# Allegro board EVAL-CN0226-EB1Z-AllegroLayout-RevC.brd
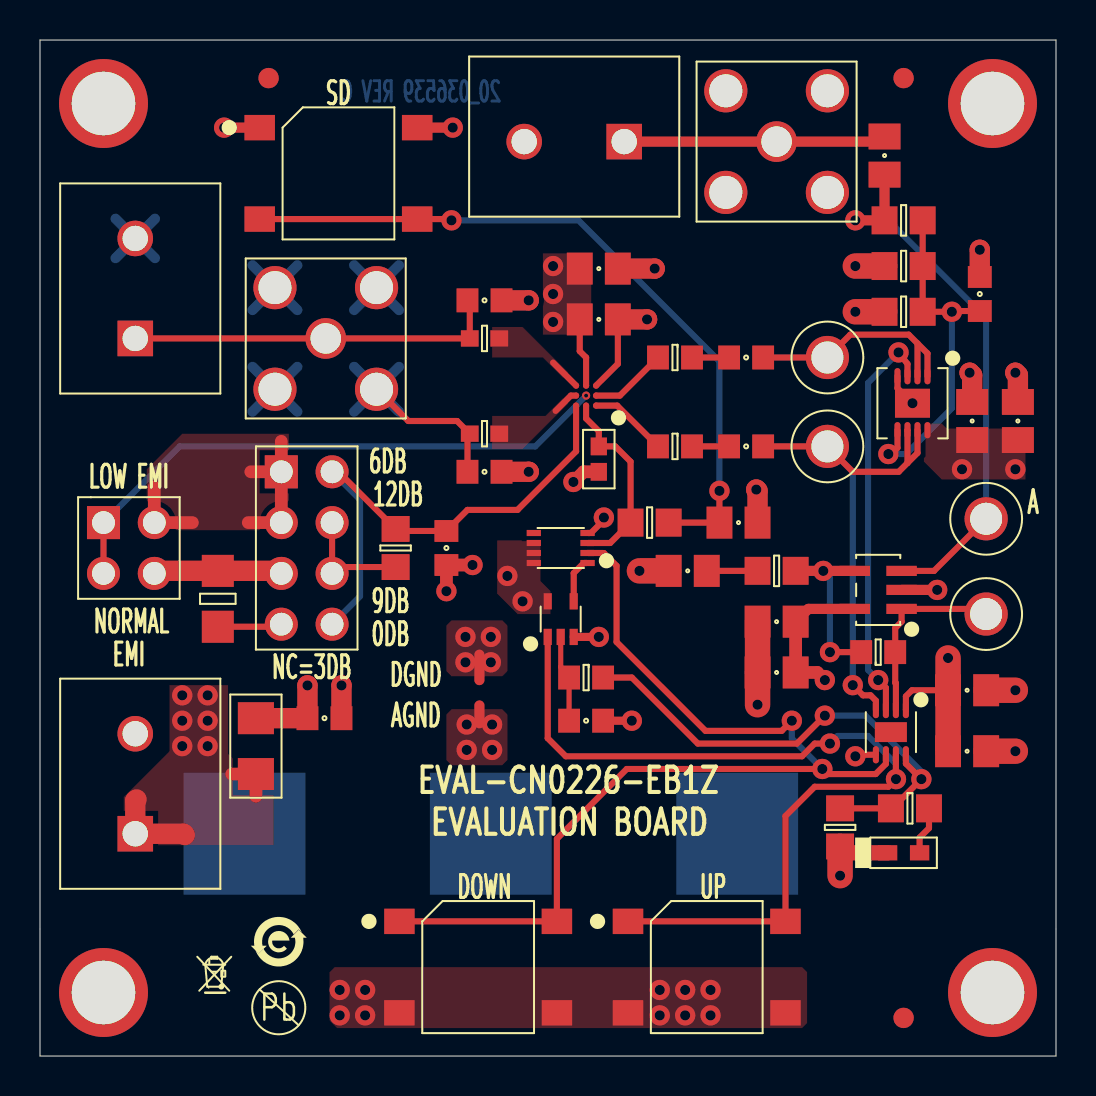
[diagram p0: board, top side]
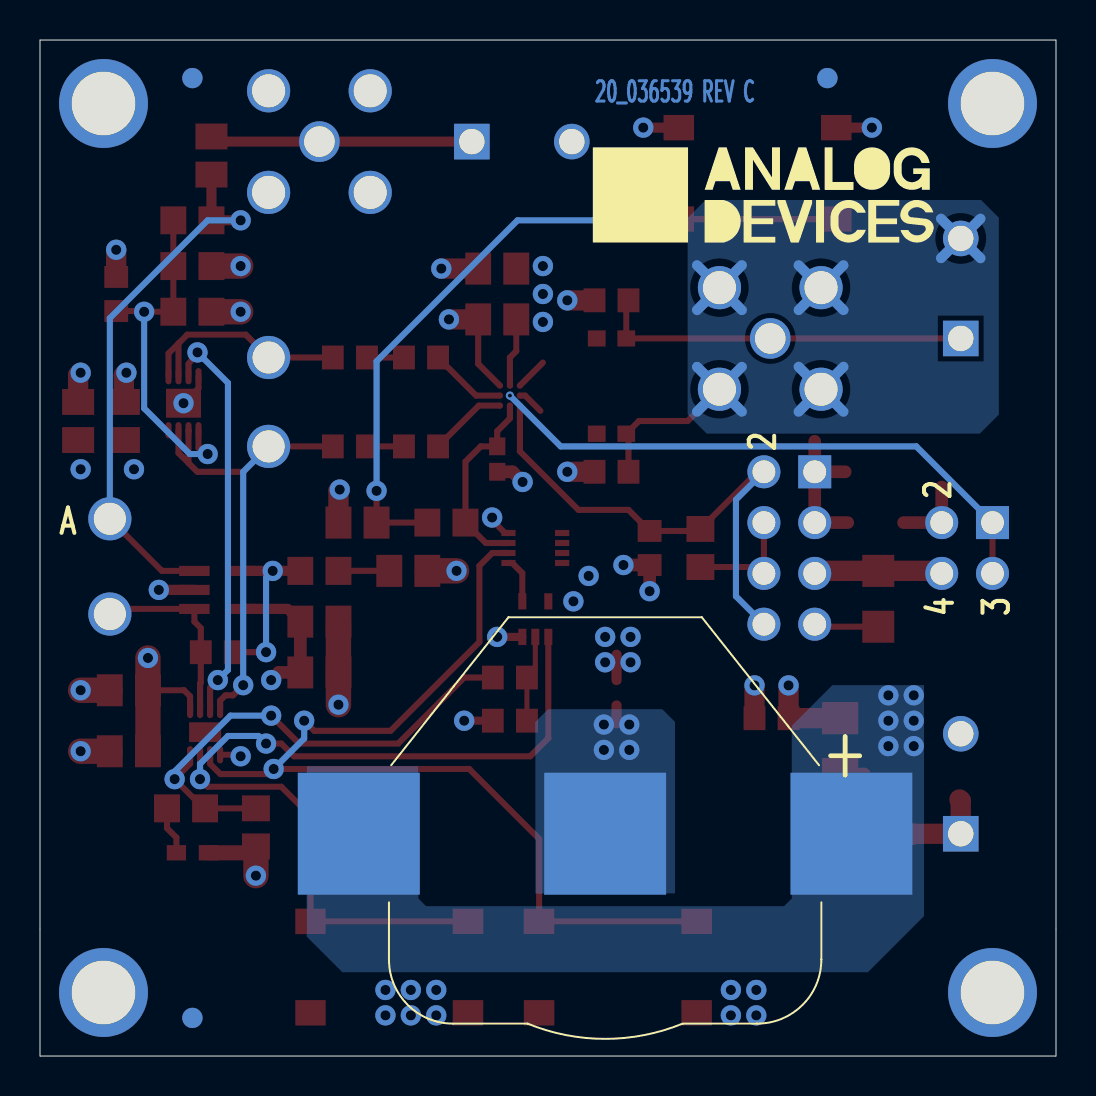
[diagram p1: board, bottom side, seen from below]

Outline 50.8 x 50.8 mm; copper layers: TOP, L2_GND, L3_POWER, BOTTOM. Coordinates in mm from the lower left corner of the outline.
Outline path: 0,50.8 0,0 50.8,0 50.8,50.8 0,50.8

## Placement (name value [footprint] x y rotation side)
A1  ADA4051-2ACPZ  [QFN8_3X3_PAD1_75X1_45]  43.62 32.64 180 top
A3  AD8515ARTZ  [SOT23-5L]  41.91 23.3 90 top
BT1  N/A  [BTCR2032_SKTBK883]  22.54 11.11 0 bottom
C1  0.1uF  [C0805]  27.94 36.83 180 top
C2  0.047uF  [C0603]  35.31 34.92 180 top
C3  0.047uF  [C0603]  35.31 30.48 180 top
C4  0.1uF  [C0805]  36.83 21.72 0 top
C5  10uF  [C0805H60]  36.83 19.18 0 top
C6  10uF  [C0805H60]  46.35 18.29 180 top
C7  0.1uF  [C0805]  46.35 15.24 180 top
C8  1uF  [C0603]  46.99 38.1 270 top
C9  0.22UF  [C0805]  42.23 45.02 270 top
C10  0.1uF  [C0805]  34.92 26.67 180 top
C11  10uF  [C0805H60]  27.94 39.37 180 top
C12  1.5uF  [C0805]  32.38 24.26 0 top
C13  1uF  [C0603]  14.22 16.89 180 top
C14  10uF  [C0805H60]  48.89 31.75 270 top
C15  0.1uF  [C0805]  46.61 31.75 270 top
C16  510pF  [C0603]  22.23 29.21 180 top
C17  510pF  [C0603]  22.23 37.78 0 top
C18  2.2uF  [C0603]  20.32 25.4 90 top
C19  0.1UF  [C0603]  27.3 16.76 0 top
DS1  LTST-C190CKT  [LED0603]  43.18 10.16 0 top
E1  220OHM  [L0603]  22.23 31.11 180 top
E2  220OHM  [L0603]  22.23 35.88 180 top
E3  600OHM AT 100MEGHZ  [L1206-3]  10.79 15.49 90 top
IN+  RED  [CNLOOPTP]  39.37 34.92 0 top
IN-  RED  [CNLOOPTP]  39.37 30.48 0 top
INPUT  RED  [CNLOOPTP]  47.31 22.1 0 top
J1  5-1814832-1  [CNTYCO1814832]  14.29 35.88 0 top
J2  5-1814832-1  [CNTYCO1814832]  36.83 45.72 0 top
J3  CTB5000/2  [CN1X2H394]  4.76 11.11 90 top
NOREF  -  []  3.17 47.62 0 top
NOREF#2  -  []  11.94 5.72 0 top
NOREF#3  -  [unnamed#2]  47.62 3.17 90 top
NOREF#4  -  []  0 50.8 0 top
NOREF#5  -  [unnamed#2]  43.18 48.9 0 top
NOREF#6  -  []  50.8 50.8 180 top
NOREF#7  -  [unnamed#2]  3.17 47.62 90 top
NOREF#8  -  []  50.8 0 90 top
NOREF#9  -  []  0 50.8 0 top
NOREF#10  -  []  50.8 0 90 top
NOREF#11  -  []  0 0 0 top
NOREF#12  -  [unnamed#2]  11.43 48.9 0 top
NOREF#13  -  []  0 50.8 270 top
NOREF#14  -  []  376.69 133.29 0 top
NOREF#15  -  []  0 0 0 top
NOREF#16  -  []  0 0 0 top
NOREF#17  -  []  8.76 4.06 0 top
NOREF#18  -  [unnamed#2]  43.18 1.91 0 top
NOREF#19  -  []  -182.88 -227.33 0 top
NOREF#20  -  []  178.44 265.18 0 top
NOREF#21  -  []  -49.78 224.92 0 top
NOREF#22  -  []  -175.26 -218.19 0 top
NOREF#23  -  [unnamed#2]  47.62 47.62 90 top
NOREF#24  -  []  3.17 47.62 0 top
NOREF#25  -  []  46.61 65.41 0 top
NOREF#26  -  [unnamed#2]  3.17 3.17 90 top
NOREF#27  -  []  -184.15 -228.6 0 top
NOREF#28  -  []  50.8 50.8 0 top
NOREF#29  -  []  11.94 2.41 0 top
NOREF#30  -  [unnamed#2]  43.18 1.91 180 bottom
NOREF#31  -  []  14.61 43.05 180 bottom
NOREF#32  -  [unnamed#2]  11.43 48.9 180 bottom
NOREF#33  -  [unnamed#2]  43.18 48.9 180 bottom
P1  CTB5000/2  [CN1X2H394]  4.76 35.88 90 top
P2  CTB5000/2  [CN1X2H394]  29.21 45.72 180 top
P3  TSW-102-08-G-D  [CNSAMTEC2X2H338LD36]  3.17 26.67 270 top
P4  TSW-104-08-T-D  [CNSAMTEC2X4H330LD36]  12.07 29.21 270 top
R1  0  [R0603]  31.75 34.92 180 top
R2  33K  [R0805]  43.18 37.21 180 top
R3  33K  [R0805]  43.18 39.5 0 top
R4  0  [R0603]  41.91 20.19 0 top
R5  47K  [R0805]  17.78 25.4 270 top
R6  44.2K  [R0402]  27.94 29.84 270 top
R7  1.8K  [R0805]  43.5 12.38 0 top
R8  110K  [R0805]  40 11.43 270 top
R9  33K  [R0805]  43.18 41.78 0 top
R10  0  [R0603]  31.75 30.48 180 top
R11  10K  [R0805]  36.83 24.26 0 top
R12  1.8K  [R0805]  30.48 26.67 0 top
R13  0  [R1206]  8.89 22.86 270 top
R14  430K  [R0603]  27.3 18.92 180 top
S1  B3S-1000  [SWB3S1000]  14.92 44.13 180 top
S2  B3S-1000  [SWB3S1000]  33.34 4.45 180 top
S3  B3S-1000  [SWB3S1000]  21.91 4.45 180 top
SNS1  SNS  [NCSNS20MIL]  21.97 18.8 270 top
TP4  RED  [CNLOOPTP]  47.31 26.86 0 top
U1  SSM2375_PRELIM  [WLCSP9]  27.3 33.02 90 top
U2  NC7SZ32P5X  [SC70-5]  26.04 21.84 0 top
U3  AD5116BCPZ5  [QFN8_2X2_PAD1_6X1]  42.54 16.19 180 top
U4  NC7SZ74K8X  [US8]  26.04 25.4 90 top

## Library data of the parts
A1 = ADA4051_2_V2: User Part Number: UPN; Tolerance: N/A; alternate symbols: (); part number: ADA4051_2_V2_SM-ADA4051-2ACPZ,E018809,QFN8_3X3_PAD1_75X1_45; tolerance: N/A
A3 = AD8515: User Part Number: UPN; Tolerance: N/A; alternate symbols: (); part number: AD8515_SM-AD8515ARTZ,E017419,SOT23-5L; tolerance: N/A
BT1 = BAT3P: User Part Number: UPN; alternate symbols: (BTCR2032_SKTBK883_ALT); part number: BAT3P_SM-N/A,3V,E017318,BTCR2032_SKTBK883
C1 C4 C7 C10 C15 = CAP: Tolerance: 5; User Part Number: UPN; alternate symbols: (); part number: CAP_SM-0.1UF,50V,5,E015576,C0805; tolerance: 5
C2 C3 = CAP: Tolerance: 5; User Part Number: UPN; alternate symbols: (); part number: CAP_SM-0.047UF,25V,5,E012692,C0603; tolerance: 5
C5 C6 C11 C14 = CAP: Tolerance: 10; User Part Number: UPN; alternate symbols: (); part number: CAP_SM-10UF,10V,10,E011045,C0805H60; tolerance: 10
C8 C13 = CAP: Tolerance: 10; User Part Number: UPN; alternate symbols: (); part number: CAP_SM-1UF,25V,10,E006992,C0603; tolerance: 10
C9 = CAP: Tolerance: 10; User Part Number: UPN; alternate symbols: (); part number: CAP_SM-0.22UF,16V,10,E000443,C0805; tolerance: 10
C12 = CAP: Tolerance: 10; User Part Number: UPN; alternate symbols: (); part number: CAP_SM-1.5UF,6.3V,10,E012852,C0805; tolerance: 10
C16 C17 = CAP: Tolerance: 5; User Part Number: UPN; alternate symbols: (); part number: CAP_SM-510PF,50V,5,E010642,C0603; tolerance: 5
C18 = CAP: Tolerance: 10; User Part Number: UPN; alternate symbols: (); part number: CAP_SM-2.2UF,6.3V,10,E006877,C0603; tolerance: 10
C19 = CAP: Tolerance: 10; User Part Number: UPN; alternate symbols: (); part number: CAP_SM-0.1UF,25V,10,E007204,C0603; tolerance: 10
DS1 = DIOLED: Tolerance: N/A; User Part Number: UPN; alternate symbols: (); part number: DIOLED_SM-LTST-C190CKT,N/A,N/A,E023763,LED0603; tolerance: N/A
E1 E2 = FERRITE: Tolerance: 25; User Part Number: UPN; alternate symbols: (); part number: FERRITE_SM-220OHM,25,E006275,L0603; tolerance: 25
E3 = FERRITE: Tolerance: 25; User Part Number: UPN; alternate symbols: (); part number: FERRITE_SM-600OHM AT 100MEGHZ,25,E026440,L1206-3; tolerance: 25
IN+ IN- INPUT TP4 = CNTP1P: Tolerance: N/A; User Part Number: UPN; alternate symbols: (); part number: CNTP1P_TH-RED,E000947,CNLOOPTP; tolerance: N/A
J1 J2 = CNBNC5P: Tolerance: N/A; User Part Number: UPN; alternate symbols: (); part number: CNBNC5P_TH-5-1814832-1,E010606,CNTYCO1814832; tolerance: N/A
J3 P1 P2 = CN2P: Tolerance: N/A; User Part Number: UPN; alternate symbols: (); part number: CN2P_TH-CTB5000/2,E017604,CN1X2H394; tolerance: N/A
P3 = CN4P_ODD_EVEN: User Part Number: UPN; Tolerance: N/A; alternate symbols: (); part number: CN4P_ODD_EVEN_TH-TSW-102-08-G-D,E006588,CNSAMTEC2X2H338LD36; tolerance: N/A
P4 = CN8P_ODD_EVEN: User Part Number: UPN; Tolerance: N/A; alternate symbols: (); part number: CN8P_ODD_EVEN_TH-TSW-104-08-T-D,E006295,CNSAMTEC2X4H330LD36; tolerance: N/A
R1 R4 R10 = RES: Tolerance: 1; User Part Number: UPN; alternate symbols: (); part number: RES_SM-0,E004207,1/16W,1,R0603; tolerance: 1
R2 R3 R9 = RES: Tolerance: 1; User Part Number: UPN; alternate symbols: (); part number: RES_SM-33K,E004180,1/10W,1,R0805; tolerance: 1
R5 = RES: Tolerance: 1; User Part Number: UPN; alternate symbols: (); part number: RES_SM-47K,E016886,1/8W,1,R0805; tolerance: 1
R6 = RES: Tolerance: 1; User Part Number: UPN; alternate symbols: (); part number: RES_SM-44.2K,E023712,1/10W,1,R0402; tolerance: 1
R7 R12 = RES: Tolerance: 0.1; User Part Number: UPN; alternate symbols: (); part number: RES_SM-1.8K,E003814,1/10W,0.1,R0805; tolerance: 0.1
R8 = RES: Tolerance: 0.1; User Part Number: UPN; alternate symbols: (); part number: RES_SM-110K,E010949,1/8W,0.1,R0805; tolerance: 0.1
R11 = RES: Tolerance: 1; User Part Number: UPN; alternate symbols: (); part number: RES_SM-10K,E003254,1/8W,1,R0805; tolerance: 1
R13 = RES: Tolerance: 5; User Part Number: UPN; alternate symbols: (); part number: RES_SM-0,E010093,1/4W,5,R1206; tolerance: 5
R14 = RES: Tolerance: 1; User Part Number: UPN; alternate symbols: (); part number: RES_SM-430K,E011184,1/10W,1,R0603; tolerance: 1
S1-S3 = SWSPST4PIN: User Part Number: UPN; Tolerance: N/A; alternate symbols: (); part number: SWSPST4PIN_SM-B3S-1000,E004572,SWB3S1000; tolerance: N/A
SNS1 = NCSENSE: User Part Number: UPN; Tolerance: N/A; alternate symbols: (); part number: NCSENSE_SM-SNS,E005724,NCSNS20MIL; tolerance: N/A
U1 = SSM2375_PRELIM: Tolerance: N/A; User Part Number: UPN; alternate symbols: (); part number: SSM2375_PRELIM_SM-SSM2375_PRELIM,E011439,WLCSP9; tolerance: N/A
U2 = ICNC7SZ32: Tolerance: N/A; User Part Number: UPN; alternate symbols: (); part number: ICNC7SZ32_SM-NC7SZ32P5X,E007299,SC70-5; tolerance: N/A
U3 = AD511X: User Part Number: UPN; Tolerance: N/A; alternate symbols: (); part number: AD511X_SM-AD5116BCPZ5,E017320,QFN8_2X2_PAD1_6X1; tolerance: N/A
U4 = CMOSNC7SZ74: Tolerance: N/A; User Part Number: UPN; alternate symbols: (); part number: CMOSNC7SZ74_SM-NC7SZ74K8X,E012799,US8; tolerance: N/A

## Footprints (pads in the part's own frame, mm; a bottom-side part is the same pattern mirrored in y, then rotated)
BTCR2032_SKTBK883
  rect 6.096x6.096 smd: 1(-12.317,0) 2(12.317,0) 3(0,0)
C0603
  rect 1.092x1.194 smd: 1(-0.851,0) 2(0.851,0)
C0805
  rect 1.295x1.6 smd: 1(-0.953,0) 2(0.953,0)
C0805H60
  rect 1.295x1.6 smd: 1(-0.953,0) 2(0.953,0)
CN1X2H394
  rect 1.778x1.778 hole 1.27: 1(0,0)
  round 1.778 hole 1.27: 2(5,0)
CNLOOPTP
  round 2.159 hole 1.6: 1(0,0)
CNSAMTEC2X2H338LD36
  rect 1.651x1.651 hole 1.143: 1(0,0)
  round 1.651 hole 1.143: 2(0,2.54) 3(2.54,0) 4(2.54,2.54)
CNSAMTEC2X4H330LD36
  rect 1.651x1.651 hole 1.143: 1(0,0)
  round 1.651 hole 1.143: 2(0,2.54) 3(2.54,0) 4(2.54,2.54) 5(5.08,0) 6(5.08,2.54) 7(7.62,0) 8(7.62,2.54)
CNTYCO1814832
  round 2.032 hole 1.524: 1(0,0)
  round 2.159 hole 1.651: 2(-2.54,2.54) 3(2.54,2.54) 4(2.54,-2.54) 5(-2.54,-2.54)
L0603
  rect 0.889x0.813 smd: 1(-0.737,0) 2(0.737,0)
L1206-3
  rect 1.6x1.803 smd: 1(-1.397,0) 2(1.397,0)
LED0603
  rect 0.965x0.762 smd: A(0.8,0) C(-0.8,0)
NCSNS20MIL
  round 0.127 smd: 1(0,0) 2(1.27,0)
QFN8_2X2_PAD1_6X1
  oval 0.305x0.864 smd: 1(-0.75,-1.13) 2(-0.25,-1.13) 3(0.25,-1.13) 4(0.75,-1.13) 5(0.75,1.13) 6(0.25,1.13) 7(-0.25,1.13) 8(-0.75,1.13)
  rect 1.6x0.991 smd: PAD(0,0)
QFN8_3X3_PAD1_75X1_45
  oval 0.305x0.813 smd: 1(-0.75,-1.35) 2(-0.25,-1.35) 3(0.25,-1.35) 4(0.75,-1.35) 5(0.75,1.35) 6(0.25,1.35) 7(-0.25,1.35) 8(-0.75,1.35)
  rect 1.753x1.448 smd: PAD(0,0)
R0402
  rect 0.889x0.813 smd: 1(-0.635,0) 2(0.635,0)
R0603
  rect 1.092x1.194 smd: 1(-0.851,0) 2(0.851,0)
R0805
  rect 1.295x1.397 smd: 1(-0.953,0) 2(0.953,0)
R1206
  rect 1.6x1.6 smd: 1(-1.397,0) 2(1.397,0)
SC70-5
  rect 0.406x0.813 smd: 1(-0.65,-0.89) 2(0,-0.89) 3(0.65,-0.89) 4(0.65,0.89) 5(-0.65,0.89)
SOT23-5L
  rect 0.508x1.524 smd: 1(-0.95,-1.17) 2(0,-1.17) 3(0.95,-1.17) 4(0.95,1.17) 5(-0.95,1.17)
SWB3S1000
  rect 1.524x1.27 smd: 1(3.937,-2.286) 2(-3.937,-2.286) 3(3.937,2.286) 4(-3.937,2.286)
unnamed#2
  round 4.445 hole 3.175 unplated: (0,0)
US8
  rect 0.305x0.711 smd: 1(-0.75,-1.343) 2(-0.25,-1.343) 3(0.25,-1.343) 4(0.75,-1.343) 5(0.75,1.343) 6(0.25,1.343) 7(-0.25,1.343) 8(-0.75,1.343)
WLCSP9
  round 0.305 smd: A1(-0.5,-0.5) A2(-0.5,0) A3(-0.5,0.5) B1(0,-0.5) B2(0,0) B3(0,0.5) C1(0.5,-0.5) C2(0.5,0) C3(0.5,0.5)

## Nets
AGND: A1.4(V-) A1.PAD A3.2(V-) BT1.3(N3) C4.1(N1) C5.1(N1) C6.1(N1) C7.1(N1) C8.1(N1) C12.1(N1) C13.1(N1) C14.1(N1) C15.1(N1) DS1.C(N) J2.2(SH1) J2.3(SH2) J2.4(SH3) J2.5(SH4) J3.2(N2) P2.2(N2) R3.1(N1) R8.2(N2) SNS1.2(N2) U3.5(GND)
DGND: C1.1(N1) C10.1(N1) C11.1(N1) C16.1(N1) C17.2(N2) C18.1(N1) C19.2(N2) P3.4(N4) P4.5(N5) R13.1(N1) S1.1(N2) S1.2(N3) SNS1.1(N1) U1.C1(PVSS) U2.3(GND) U4.4(GND)
VDD: A1.8(V+) A3.5(V+) C4.2(N2) C5.2(N2) C6.2(N2) C7.2(N2) C13.2(N2) C14.2(N2) C15.2(N2) E3.2(N2) P3.2(N2) P4.1(N1) P4.3(N3) R2.2(N2) S2.3(N5) S2.4(N4) S3.3(N5) S3.4(N4) U2.5(VCC) U3.1(VDD) U4.6(CLR_N) U4.7(PR_N) U4.8(VCC)
VDD1: BT1.1(N1) BT1.2(N2) C1.2(N2) C11.2(N2) E3.1(N1) J3.1(N1) R6.2(N2) U1.C2(PVDD)
A: A3.3(+IN) C9.2(N2) R9.1(N1) TP4.1(N1)
ASE_N: R7.1(N1) R8.1(N1) R14.1(N1) U3.8(ASE_N)
ASE_N_DEB: C19.1(N1) R14.2(N2) U2.2(B)
EDGE: P3.1(N1) P3.3(N3) U1.B2(EDGE)
GAIN: C18.2(N2) P4.2(N2) P4.8(N8) R5.1(N1) U1.A3(GAIN)
IN+: A1.1(OUT A) A1.2(-IN A) C2.1(N1) IN+.1(N1)
IN-: A1.6(-IN B) A1.7(OUT B) C3.1(N1) IN-.1(N1) U3.4(B)
INPUT: A3.1(OUT) INPUT.1(N1) R4.2(N2) U3.2(A)
PD: S3.1(N2) S3.2(N3) U3.6(PD) U4.2(D)
PU: S2.1(N2) S2.2(N3) U2.1(A) U3.7(PU)
SD_N: R6.1(N1) R12.1(N1) U1.A2(STDNB) U4.3(Q_N)
UNNAMED_2_AD8515_I52_: A3.4(-IN) R4.1(N1) R11.2(N2)
UNNAMED_2_ADA40512V2_I34_: A1.5(+IN B) C8.2(N2) R2.1(N1) R3.2(N2) R9.2(N2)
UNNAMED_2_CAP_I47_N1: C9.1(N1) J2.1(CNTR) P2.1(N1)
UNNAMED_2_CAP_I54_N2: C12.2(N2) R11.1(N1)
UNNAMED_2_CAP_I65_N2: C2.2(N2) R1.1(N1)
UNNAMED_2_CAP_I66_N2: C3.2(N2) R10.1(N1)
UNNAMED_2_CAP_I80_N2: C10.2(N2) R12.2(N2) S1.3(N5) S1.4(N4)
UNNAMED_2_CAP_I90_N2: C16.2(N2) E1.2(N2) J1.2(SH1) J1.3(SH2) J1.4(SH3) J1.5(SH4) P1.2(N2)
UNNAMED_2_CAP_I91_N1: C17.1(N1) E2.2(N2) J1.1(CNTR) P1.1(N1)
UNNAMED_2_CMOSNC7SZ74_I106_CK: U2.4(OUT) U4.1(CK)
UNNAMED_2_CN8PODDEVEN_I110_N4: P4.4(N4) P4.6(N6) R5.2(N2)
UNNAMED_2_CN8PODDEVEN_I110_N7: P4.7(N7) R13.2(N2)
UNNAMED_2_DIOLED_I100_P: DS1.A(P) R7.2(N2)
UNNAMED_2_FERRITE_I92_N1: E1.1(N1) U1.B3(OUTN)
UNNAMED_2_FERRITE_I93_N1: E2.1(N1) U1.C3(OUTP)
UNNAMED_2_RES_I62_N2: R1.2(N2) U1.B1(IP)
UNNAMED_2_RES_I63_N2: R10.2(N2) U1.A1(IN)
W: A1.3(+IN A) U3.3(W)

Pads without a net: U3 PAD; U4 5

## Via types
v1: diameter 0.406, hole 0.203, TOP to BOTTOM, 1 via
v2: diameter 1.016, hole 0.508, TOP to BOTTOM, 77 vias

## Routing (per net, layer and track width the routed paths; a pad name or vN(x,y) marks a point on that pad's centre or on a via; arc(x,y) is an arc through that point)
AGND: length 53.9
  TOP w0.305: v2(43.62,32.64) 42.87,33.39 A1.4 ; v2(40.77,14.99) 40.84,15.06 U3.5
  TOP w0.508: SNS1.2 21.97,16.64 ; A3.2 v2(44.86,23.3)
  TOP w0.762: R8.2 40.32,10.16 DS1.C
  TOP w1.016: C14.1 48.89,34.04 v2(48.77,34.16) ; C15.1 46.61,34.04 v2(46.48,34.16) ; C13.1 v2(15.07,18.53) ; C8.1 v2(46.99,40.31)
  TOP w1.27: R3.1 v2(40.77,39.5) ; C4.1 C5.1 v2(35.88,17.56) ; C12.1 v2(29.97,24.26) ; C6.1 v2(48.77,18.29) ; v2(40,9.02) R8.2 ; C7.1 v2(48.77,15.24)
  L2_GND w0.508: 38.25,44.3 J2.4 ; J2.4 38.25,42.06 ; J2.4 40.49,44.3 ; J3.2 5.75,15.13 ; J3.2 5.75,17.1 ; J3.2 3.78,15.13 ; J3.2 3.78,17.1 ; 35.41,47.14 J2.2 33.17,47.14 ; 33.17,44.3 J2.5 ; J2.5 33.17,42.06 ; J2.5 35.41,44.3 ; J2.5 35.41,42.06 ; 38.25,47.14 J2.3 40.49,47.14 ; 23.22,44.73 P2.2 ; P2.2 23.22,46.71 ; P2.2 25.2,46.71 ; P2.2 25.2,44.73
  vias: v2(21.34,16.57) v2(21.34,15.3) v2(22.61,16.57) v2(22.61,15.3)
DGND: length 39.9
  TOP w0.305: C1.1 28.89,34.61 U1.C1 ; U4.4 27.55,26.15 28.19,26.8 v2(28.19,26.92)
  TOP w0.406: C19.2 v2(29.59,16.76) ; U2.3 v2(27.94,20.95)
  TOP w0.508: SNS1.1 21.97,20.07 ; S1.1 v2(9.21,46.42) ; S1.2 v2(20.64,46.42)
  TOP w0.635: v2(21.63,24.55) C18.1 v2(20.32,23.24)
  TOP w1.016: C10.1 35.88,28.26 v2(35.81,28.32) ; 12.07,24.13 11.94,24.26 R13.1 5.84,24.26 5.71,24.13 ; C1.1 v2(30.35,36.83) ; C11.1 v2(30.73,39.37) ; C16.1 v2(24.43,29.21) ; C17.2 v2(24.43,37.78)
  L2_GND w0.508: 5.71,24.13 6.66,25.07 ; 5.71,24.13 4.77,23.19 ; 5.71,24.13 6.66,23.19 ; 5.71,24.13 4.77,25.07 ; 12.07,24.13 13.01,25.07 ; 12.07,24.13 11.12,23.19 ; 12.07,24.13 11.12,25.07 ; 12.07,24.13 13.01,23.19
  vias: v2(21.27,20.95) v2(21.27,19.68) v2(22.54,20.95) v2(22.54,19.68)
VDD: length 42.2
  TOP w0.305: U3.1 43.3,17.98 43.6,18.29 C6.2
  TOP w0.508: C4.2 38.42,22.35 A3.5
  TOP w0.635: C4.2 C5.2 38.86,19.18 v2(39.24,18.8) ; 10.41,26.67 P4.3 P4.1 ; 5.71,28.45 P3.2 7.62,26.67 ; P4.1 12.07,30.73 ; P4.1 10.54,29.21
  TOP w1.016: E3.2 C13.2 v2(13.37,18.53)
  TOP w1.27: R2.2 v2(40.77,37.21) ; v2(45.4,19.9) C6.2 C7.2
  L3_POWER w0.508: 11.12,25.73 P4.3 ; P4.3 13.01,25.73 ; P4.3 11.12,27.61 ; P4.3 13.01,27.61 ; 11.12,28.27 P4.1 ; P4.1 11.12,30.15 ; P4.1 13.01,28.27 ; P4.1 13.01,30.15
  vias: v2(14.99,3.3) v2(14.99,2.03) v2(16.26,3.3) v2(16.26,2.03) v2(23.37,24) v2(24.13,22.73) v2(30.99,3.3) v2(30.99,2.03) v2(32.26,3.3) v2(32.26,2.03) v2(33.53,3.3) v2(33.53,2.03) v2(46.1,29.34) v2(48.77,29.34)
VDD1: length 17
  TOP w0.305: U1.C2 27.3,34.92 26.99,35.24 C1.2
  TOP w0.635: v2(26.67,28.7) 27.18,29.21 R6.2 ; 10.79,12.99 E3.1 9.59,14.1
  TOP w1.016: 7.24,11.05 7.18,11.11 J3.1 4.76,12.76 4.83,12.83
  L3_POWER w0.508: 3.78,10.13 J3.1 ; J3.1 5.75,10.13 ; J3.1 5.75,12.1 ; J3.1 3.78,12.1
  vias: v2(7.11,18.03) v2(7.11,16.76) v2(7.11,15.49) v2(8.38,18.03) v2(8.38,16.76) v2(8.38,15.49) v2(25.65,39.5) v2(25.65,38.1) v2(25.65,36.7)
A: length 27.7
  TOP w0.305: TP4.1 44.7,24.25 A3.3
  TOP w0.508: v2(40.77,41.78) R9.1 C9.2
  BOTTOM w0.305: TP4.1 47.31,36.89 42.42,41.78 v2(40.77,41.78)
ASE_N: length 25.6
  TOP w0.305: R14.1 29.59,18.92 32.89,15.62 37.85,15.62 v2(39.24,17.02) ; U3.8 43.3,14.62 v2(44.07,13.84) 42.61,12.38 R7.1 R8.1
  BOTTOM w0.305: v2(44.07,13.84) 44.07,14.22 41.27,17.02 v2(39.24,17.02)
ASE_N_DEB: length 4.4
  TOP w0.254: U2.2 26.04,19.47 26.45,19.05 R14.2 C19.1
EDGE: length 29.3
  TOP w0.305: 3.17,24.13 P3.1
  BOTTOM w0.305: v1(27.3,33.02) 24.77,30.48 6.98,30.48 P3.1
GAIN: length 26.1
  TOP w0.305: P4.2 14.92,29.21 R5.1 17.88,26.25 C18.2 21.37,27.3 23.88,27.3 26.8,30.23 U1.A3
  BOTTOM w0.305: P4.2 16,27.81 16,22.99 P4.8
IN+: length 11.9
  TOP w0.305: A1.2 43.87,35.63 ; 43.87,35.63 43.43,36.07 40.51,36.07 IN+.1 C2.1 ; 43.87,35.63 44.37,35.13 A1.1
IN-: length 25.8
  TOP w0.305: 43.37,29.65 43.87,30.15 A1.7 ; 43.37,29.65 A1.6 ; 43.37,29.65 42.93,29.21 40.64,29.21 IN-.1 C3.1 ; U3.4 41.79,17.77 41.53,18.03 41.15,18.03 v2(40.64,18.54)
  BOTTOM w0.305: v2(40.64,18.54) 40.64,29.21 IN-.1
INPUT: length 9.5
  TOP w0.305: INPUT.1 47.05,22.35 A3.1 43.08,21.72 42.76,21.4 R4.2 42.76,18.67 42.79,18.63 U3.2
PD: length 50.1
  TOP w0.305: v2(37.59,16.76) 37.08,16.26 33.27,16.26 28.83,20.7 28.83,24.51 28.19,25.15 U4.2 ; U3.6 42.3,14.61 41.78,14.1 39.37,14.1 v2(39.12,14.35) 29.34,14.35 25.84,10.86 S3.2 S3.1
  BOTTOM w0.305: v2(37.59,16.76) 37.59,15.88 v2(39.12,14.35)
PU: length 45.3
  TOP w0.305: v2(39.5,15.62) 38.73,15.62 38.1,14.99 26.29,14.99 25.39,15.89 U2.1 ; S2.1 S2.2 37.27,12 38.73,13.46 42.42,13.46 v2(42.8,13.84) 42.79,13.85 U3.7
  BOTTOM w0.305: v2(39.5,15.62) 39.88,16 41.4,16 42.8,14.6 v2(42.8,13.84)
SD_N: length 9.8
  TOP w0.305: U4.3 28.51,25.65 R12.1 29.53,29.72 28.77,30.48 R6.1 27.94,31.24 27.3,31.88 U1.A2
UNNAMED_2_AD8515_I52_: length 8.7
  TOP w0.305: R4.1 v2(39.5,20.19)
  TOP w0.508: R11.2 39.16,24.26 v2(39.16,24.25) A3.4
  BOTTOM w0.305: v2(39.16,24.25) 39.5,23.92 v2(39.5,20.19)
UNNAMED_2_ADA40512V2_I34_: length 17.9
  TOP w0.305: A1.5 42.87,30.4 42.6,30.13 v2(42.42,30.1) ; R9.2 R3.2 R2.1 v2(45.59,37.21) 45.63,37.25 C8.2
  BOTTOM w0.305: v2(45.59,37.21) 45.59,32.38 43.31,30.1 v2(42.42,30.1)
UNNAMED_2_CAP_I47_N1: length 13.1
  TOP w0.508: P2.1 J2.1 41.97,45.72 42.23,45.97
UNNAMED_2_CAP_I54_N2: length 2.5
  TOP w0.305: C12.2 R11.1
UNNAMED_2_CAP_I65_N2: length 1.9
  TOP w0.305: R1.1 C2.2
UNNAMED_2_CAP_I66_N2: length 1.9
  TOP w0.305: R10.1 C3.2
UNNAMED_2_CAP_I80_N2: length 36.5
  TOP w0.305: S1.3 S1.4 20.51,41.85 v2(20.57,41.78) ; R12.2 C10.2 v2(33.97,28.26)
  BOTTOM w0.305: v2(20.57,41.78) 26.92,41.78 33.97,34.73 v2(33.97,28.26)
UNNAMED_2_CAP_I90_N2: length 38.4
  TOP w0.305: C16.2 21.37,31 E1.2 20.85,31.75 18.41,31.75 J1.4
  BOTTOM w0.508: J1.3 17.95,39.54 ; J1.3 15.71,39.54 ; J1.3 15.71,37.3 ; J1.3 17.95,37.3 ; J1.4 17.95,32.22 ; J1.4 15.71,32.22 ; J1.4 17.95,34.46 ; J1.4 15.71,34.46 ; 3.78,41.86 P1.2 ; P1.2 5.75,41.86 ; P1.2 5.75,39.89 ; P1.2 3.78,39.89 ; J1.5 12.87,32.22 ; J1.5 12.87,34.46 ; J1.5 10.63,34.46 ; J1.5 10.63,32.22 ; 10.63,37.3 J1.2 ; J1.2 10.63,39.54 ; J1.2 12.87,39.54 ; J1.2 12.87,37.3
UNNAMED_2_CAP_I91_N1: length 18.7
  TOP w0.305: P1.1 J1.1 E2.2 21.49,37.67 C17.1
UNNAMED_2_CMOSNC7SZ74_I106_CK: length 2.3
  TOP w0.305: U4.1 27.19,24.65 26.68,24.14 U2.4
UNNAMED_2_CN8PODDEVEN_I110_N4: length 5.8
  TOP w0.305: R5.2 14.92,24.45 14.61,24.13 P4.4
UNNAMED_2_CN8PODDEVEN_I110_N7: length 3.2
  TOP w0.305: R13.2 11.94,21.46 P4.7
UNNAMED_2_DIOLED_I100_P: length 2.4
  TOP w0.305: R7.2 44.45,11.39 43.98,10.92 DS1.A
UNNAMED_2_FERRITE_I92_N1: length 1.3
  TOP w0.305: U1.B3 26.54,33.02 25.78,32.26
UNNAMED_2_FERRITE_I93_N1: length 1.6
  TOP w0.305: U1.C3 25.65,34.67
UNNAMED_2_RES_I62_N2: length 3.9
  TOP w0.305: R1.2 28.99,33.02 U1.B1
UNNAMED_2_RES_I63_N2: length 3.9
  TOP w0.305: U1.A1 28.86,32.52 R10.2
W: length 20.2
  TOP w0.305: U3.3 42.3,18.41 v2(41.91,18.8) ; v2(42.93,35.18) 43.37,34.6 A1.3
  BOTTOM w0.305: v2(42.93,35.18) 41.4,33.66 41.4,19.3 v2(41.91,18.8)

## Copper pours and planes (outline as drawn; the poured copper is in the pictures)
AGND on TOP: 23.11,17.34 20.57,17.34 20.32,17.08 20.32,14.8 20.57,14.54 23.11,14.54 23.37,14.8 23.37,17.08
AGND on BOTTOM: 19.05,16.7 19.05,8.13 26.04,8.13 26.04,16.7 25.4,17.34 19.69,17.34
AGND on L2_GND: 6.35,1.27 6.35,4.45 4.45,6.35 1.27,6.35 1.27,12.7 1.27,12.7 1.27,19.05 16.51,19.05 16.51,17.78 24.26,17.78 24.26,14.86 32,14.86 32.13,14.99 32.13,22.61 32,22.73 28.57,22.73 28.57,24.77 37.46,24.77 37.46,41.27 22.23,41.27 22.23,49.53 22.23,49.53 44.45,49.53 44.45,46.35 46.35,44.45 49.53,44.45 49.53,12.7 49.53,12.7 49.53,6.35 46.35,6.35 44.45,4.45 44.45,1.27 34.29,1.27 34.29,4.06 30.23,4.06 30.23,1.27 17.02,1.27 17.02,4.06 14.22,4.06 14.22,1.27
DGND on TOP: 23.37,21.53 23.11,21.78 20.57,21.78 20.32,21.53 20.32,19.24 20.57,18.99 23.11,18.99 23.37,19.24
DGND on L2_GND: 1.27,44.45 4.45,44.45 6.35,46.35 6.35,49.53 21.59,49.53 21.59,40.64 36.83,40.64 36.83,25.4 27.94,25.4 27.94,22.23 28.07,22.1 31.5,22.1 31.62,21.97 31.62,15.62 31.37,15.37 24.89,15.37 24.89,18.41 17.14,18.41 17.14,19.68 1.27,19.68 1.27,19.69
VDD on TOP: 5.33,26.29 5.33,29.34 7.11,31.11 12.45,31.11 12.45,26.29
VDD on TOP: 14.73,4.45 38.1,4.45 38.35,4.19 38.35,1.65 38.1,1.4 14.86,1.4 14.48,1.78 14.48,4.19
VDD on TOP: 45.08,28.83 44.2,29.72 44.2,31.62 45.08,31.62 45.34,31.37 49.28,31.37 49.28,28.83
VDD on TOP: 25.02,25.78 22.86,25.78 22.86,23.11 23.88,22.1 25.53,22.1 25.53,23.24 25.02,23.75
VDD on L3_POWER: 29.85,49.53 44.45,49.53 44.45,46.35 46.35,44.45 49.53,44.45 49.53,12.7 49.53,12.7 49.53,6.35 46.35,6.35 44.45,4.45 44.45,1.27 12.07,1.27 12.07,18.41 10.16,18.41 10.16,31.11 20.32,31.11 20.32,27.3 29.85,27.3
VDD1 on TOP: 6.48,18.54 9.4,18.54 9.4,15.11 9.78,14.73 11.68,14.73 11.68,10.54 4.19,10.54 4.19,12.95 6.48,15.24
VDD1 on TOP: 25.15,36.07 25.15,40.13 27.56,40.13 27.56,36.07
VDD1 on BOTTOM: 9.4,4.19 6.6,6.98 6.6,18.54 11.18,18.54 13.21,16.51 13.21,7.87 13.59,7.49 31.5,7.49 31.88,7.87 31.88,14.48 37.46,14.48 37.46,5.97 35.69,4.19
VDD1 on L3_POWER: 1.27,6.35 1.27,13.97 1.27,13.97 1.27,44.45 4.45,44.45 6.35,46.35 6.35,49.53 29.21,49.53 29.21,27.94 20.96,27.94 20.96,31.75 9.52,31.75 9.52,17.78 11.43,17.78 11.43,1.27 6.35,1.27 6.35,4.45 4.45,6.35
UNNAMED_2_CAP_I90_N2 on BOTTOM: 2.86,41.91 2.86,32.07 3.81,31.11 17.46,31.11 18.41,32.07 18.41,41.91 17.53,42.8 3.75,42.8
UNNAMED_2_FERRITE_I92_N1 on TOP: 26.16,32.89 26.42,32.64 24.13,30.35 22.61,30.35 22.61,32 25.27,32
UNNAMED_2_FERRITE_I93_N1 on TOP: 22.61,36.45 22.61,34.92 25.15,34.92 26.16,33.91 26.42,34.16 24.13,36.45

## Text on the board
BOTTOM: 20_036539 REV C
Ref Des/Silkscreen Bottom: A
Ref Des/Silkscreen Top: EMI | NC=3DB | SD | 6DB | 9DB | 0DB | 12DB | DGND | AGND | DOWN | UP | A | EVAL-CN0226-EB1Z | EVALUATION BOARD
PAGE_OUTLINE: 0.062" THICK LAYERED | STRESS NICKEL | FLASH GOLD OVER LOW | 5-15 MICRO INCHES | MATERIAL PER NOTES/ | STACK UP | N/A | JUL13 | NOV12 | MAY13 | B | C | AS PER ECR-056711 | AS PER ECR-065688 | OCT15 | NOV16 | M. SAMERA | NOTES: | 1. THE BOARD SIZE MAY VARY TO COMPENSATE THE COMPONENTS DENSITY OF THE CIRCUIT. | 2. THE BOARD MAY EXTEND TO THE RIGHT AND LOWER PORTION IF THERE IS A NEED TO CHANGE THE BOARD SIZE. | 3. J1 CONNECTOR LOCATION IS FIXED WITH REFERENCE TO THE DISTANCE ON BOARD EDGE ON THE UPPER LEFT PORTION.
DIMENSION: (REF) | SEE NOTE 15 | DIA MAX
DISPLAY_BOTTOM: L2 GND | 08-      -07
User.6: L3 POWER | 08-      -08
User.7: COPLANAR ON TOP SIDE WITHIN .001 INCH PRIOR TO FINAL PLATING. | 15.    THRU VIAS FILLED USING NON-CONDUCTIVE FILL AND PLATED OVER,
User.17: 1 | 2 | 3 | 4 | 5 | 6 | 7 | 8 | 9 | 10 | 11 | 12 | IN1 | IN2 | IN3 | IN4 | S1 | D1 | S2 | D2 | S3 | D3 | S4 | D4 | VDD | VSS | GND | PAD | 1. DO NOT INSTALL R4 AND J1. | PIN          SIGNAL | 9. ADD ADG1611 LFCSP WITH CONNECTION BELOW: | 8. ADD PMOD CONNECTOR WITH CONNECTION BELOW: | 2. REMOVE R9,R10 (E003488) AND C10,C11 (E000442). | SCL | SUPPLY | DGND | GPIO0 | GPIO2 | 5V | SDA | VIO | AGND | GPIO1 | GPIO3 | 3.3V | PIN NAMES       SIGNAL/CONNECTION PINS | -SUPPLY | TO P5.2 | TO P7.1 | TO P7.2 | TO P7.3 | TO P7.4 | TO P6.2 | TO P5.1 | TO P6.1 | 6. ADD SECOND P10 CONNECTOR IN SERIES WITH P10. THUS P10.1 AND P10.2. | 4. REPLACE 10UF TANTALUM CAPS(E000714) TO 10UF CERAMIC CAPS (E018347). | THE FOLLOWING CHANGES WERE MADE TO REV.A BOARDS TO BRING TEHEM TO REV.B: | 7. ADD TESTPOINTS (DO NOT INSTALL) IN U6.7, U3.7, U9.7 AND BETWWEN C34 AND R6. | 3. REPLACE AD8659 WITH AD8643, C35 AND C36 (E000442) WITH O OHM RESISTOR, R16 AND R17. | 5. ADD 100K RESISTORS(R8 AND R1 RESPECTIVELY) BETWEEN U3.1 AND AGND AND U9.4 AND AGND AND 10M RESISTOR(R10) TO P6.1 AND AGND. | 13 | REWORK | A
User.24: FIGURE | SIZE | 8.0 | 20.0 | 20.01 | 45.0 | 50.0 | 60.0 | 63.0 | 65.0 | 125.0 | PLATED | NON-PLATED | FINISHED HOLES IN MILS | ALL UNITS ARE IN MILS | QTY | 1 | 76 | 12 | 6 | 2 | 4 | 8 | TOLERANCE/NOTES
